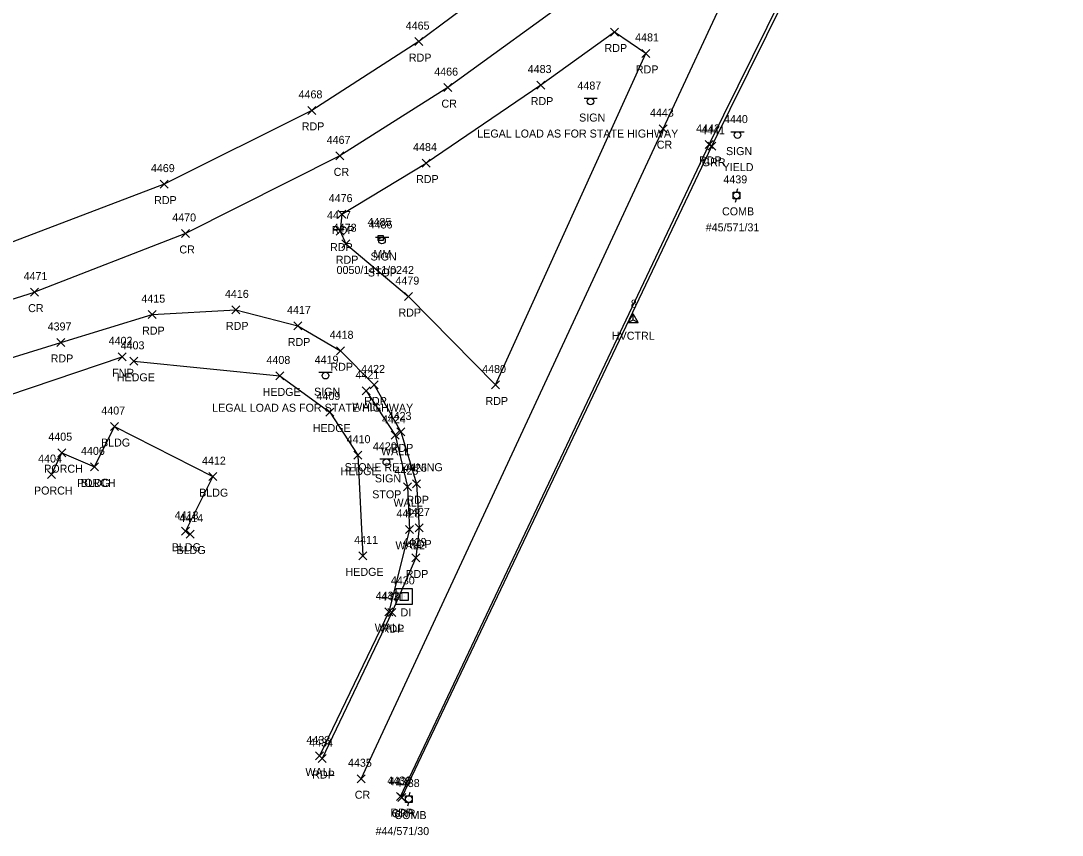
# Model space of a CAD drawing. Extents: x 1690689 to 1696275, y 438760 to 444007.
# Drawn here: x 1696011 to 1696271.3, y 443474.4 to 443678 of the extents above; entities that cross this region are included whole.
import ezdxf

# ---------------------------------------------------------------- set-up
doc = ezdxf.new("R2010")
doc.units = 0
for name, color, linetype in [('C_A', 7, 'Continuous'), ('C_I', 7, 'Continuous'), ('CPSM', 7, 'Continuous'), ('D_A', 7, 'Continuous'), ('D_I', 7, 'Continuous'), ('DS', 7, 'Continuous'), ('L_A', 7, 'Continuous'), ('L_C', 7, 'Continuous'), ('L_I', 7, 'Continuous'), ('L_TIC', 7, 'Continuous'), ('LAHR', 7, 'Continuous'), ('LBC', 7, 'Continuous'), ('LBF', 7, 'Continuous'), ('LFNC', 7, 'Continuous'), ('LW', 7, 'Continuous'), ('P_A', 7, 'Continuous'), ('P_I', 7, 'Continuous'), ('P_TIC', 7, 'Continuous'), ('PET', 7, 'Continuous'), ('PRC', 7, 'Continuous'), ('R_A', 7, 'Continuous'), ('R_I', 7, 'Continuous'), ('R_TIC', 7, 'Continuous'), ('RGR', 7, 'Continuous'), ('S_A', 7, 'Continuous'), ('S_C', 7, 'Continuous'), ('S_I', 7, 'Continuous'), ('SRM', 7, 'Continuous'), ('SSGN', 7, 'Continuous'), ('U_A', 7, 'Continuous'), ('U_C', 7, 'Continuous'), ('U_I', 7, 'Continuous'), ('UP', 7, 'Continuous')]:
    doc.layers.add(name, color=color, linetype=linetype)

msp = doc.modelspace()

# ---------------------------------------------------------------- linework, layer by layer
at = {"layer": 'CPSM'}
for p, q in [((1696162.82, 443602.55), (1696164.07, 443604.72)), ((1696165.32, 443602.55), (1696164.07, 443604.72)), ((1696164.07, 443603.27), (1696164.07, 443604.72)), ((1696162.82, 443602.55), (1696164.07, 443603.27)), ((1696162.82, 443602.55), (1696165.32, 443602.55)), ((1696164.07, 443603.27), (1696164.07, 443603.27)), ((1696164.07, 443603.27), (1696165.32, 443602.55))]:
    msp.add_line(p, q, dxfattribs=at)
at = {"layer": 'DS'}
for p, q in [((1696104.89, 443536.11), (1696108.89, 443536.11)), ((1696104.89, 443532.11), (1696104.89, 443536.11)), ((1696108.89, 443536.11), (1696108.89, 443532.11)), ((1696105.89, 443533.11), (1696105.89, 443535.11)), ((1696105.89, 443535.11), (1696107.89, 443535.11)), ((1696107.89, 443533.11), (1696105.89, 443533.11)), ((1696106.89, 443534.11), (1696106.89, 443534.11)), ((1696106.89, 443534.11), (1696106.89, 443534.11)), ((1696107.89, 443535.11), (1696107.89, 443533.11)), ((1696108.89, 443532.11), (1696104.89, 443532.11))]:
    msp.add_line(p, q, dxfattribs=at)
at = {"layer": 'L_TIC'}
for points in [[(1696035.34, 443593), (1696037.34, 443595)], [(1696037.34, 443593), (1696035.34, 443595)], [(1696038.33, 443591.87), (1696040.33, 443593.87)], [(1696040.33, 443591.87), (1696038.33, 443593.87)], [(1696074.78, 443588.22), (1696076.78, 443590.22)], [(1696076.78, 443588.22), (1696074.78, 443590.22)], [(1696096.39, 443584.51), (1696098.39, 443586.51)], [(1696098.39, 443584.51), (1696096.39, 443586.51)], [(1696087.29, 443579.19), (1696089.29, 443581.19)], [(1696089.29, 443579.19), (1696087.29, 443581.19)], [(1696033.49, 443575.57), (1696035.49, 443577.57)], [(1696035.49, 443575.57), (1696033.49, 443577.57)], [(1696103.57, 443573.41), (1696105.57, 443575.41)], [(1696105.57, 443573.41), (1696103.57, 443575.41)], [(1696020.26, 443569.03), (1696022.26, 443571.03)], [(1696022.26, 443569.03), (1696020.26, 443571.03)], [(1696094.26, 443568.41), (1696096.26, 443570.41)], [(1696096.26, 443568.41), (1696094.26, 443570.41)], [(1696028.48, 443565.48), (1696030.48, 443567.48)], [(1696030.48, 443565.48), (1696028.48, 443567.48)], [(1696028.48, 443565.48), (1696030.48, 443567.48)], [(1696030.48, 443565.48), (1696028.48, 443567.48)], [(1696017.71, 443563.57), (1696019.71, 443565.57)], [(1696019.71, 443563.57), (1696017.71, 443565.57)], [(1696058.02, 443563.04), (1696060.02, 443565.04)], [(1696060.02, 443563.04), (1696058.02, 443565.04)], [(1696106.71, 443560.53), (1696108.71, 443562.53)], [(1696108.71, 443560.53), (1696106.71, 443562.53)], [(1696051.18, 443549.4), (1696053.18, 443551.4)], [(1696053.18, 443549.4), (1696051.18, 443551.4)], [(1696107.19, 443549.86), (1696109.19, 443551.86)], [(1696109.19, 443549.86), (1696107.19, 443551.86)], [(1696052.36, 443548.69), (1696054.36, 443550.69)], [(1696054.36, 443548.69), (1696052.36, 443550.69)], [(1696095.5, 443543.24), (1696097.5, 443545.24)], [(1696097.5, 443543.24), (1696095.5, 443545.24)], [(1696102.01, 443529.28), (1696104.01, 443531.28)], [(1696104.01, 443529.28), (1696102.01, 443531.28)], [(1696084.68, 443493.22), (1696086.68, 443495.22)], [(1696086.68, 443493.22), (1696084.68, 443495.22)]]:
    msp.add_lwpolyline(points, dxfattribs=at)
at = {"layer": 'LAHR'}
msp.add_lwpolyline([(1696039.33, 443592.87), (1696075.78, 443589.22), (1696088.29, 443580.19), (1696095.26, 443569.41), (1696096.5, 443544.24)], dxfattribs=at)
at = {"layer": 'LBC'}
msp.add_lwpolyline([(1696029.48, 443566.48), (1696034.49, 443576.57), (1696059.02, 443564.04), (1696052.18, 443550.4), (1696053.36, 443549.69)], dxfattribs=at)
at = {"layer": 'LBF'}
msp.add_lwpolyline([(1696018.71, 443564.57), (1696021.26, 443570.03), (1696029.48, 443566.48)], dxfattribs=at)
at = {"layer": 'LFNC'}
msp.add_lwpolyline([(1695959.01, 443561.01), (1695960.28, 443568.97), (1695966.01, 443573.58), (1695990.72, 443578.55), (1696036.34, 443594)], dxfattribs=at)
at = {"layer": 'LW'}
msp.add_lwpolyline([(1696097.39, 443585.51), (1696104.57, 443574.41), (1696107.71, 443561.53), (1696108.19, 443550.86), (1696103.01, 443530.28), (1696085.68, 443494.22)], dxfattribs=at)
at = {"layer": 'P_TIC'}
for points in [[(1696109.55, 443671.79), (1696111.55, 443673.79)], [(1696111.55, 443671.79), (1696109.55, 443673.79)], [(1696158.44, 443674.19), (1696160.44, 443676.19)], [(1696160.44, 443674.19), (1696158.44, 443676.19)], [(1696166.28, 443668.85), (1696168.28, 443670.85)], [(1696168.28, 443668.85), (1696166.28, 443670.85)], [(1696116.73, 443660.29), (1696118.73, 443662.29)], [(1696118.73, 443660.29), (1696116.73, 443662.29)], [(1696139.99, 443660.93), (1696141.99, 443662.93)], [(1696141.99, 443660.93), (1696139.99, 443662.93)], [(1696082.77, 443654.61), (1696084.77, 443656.61)], [(1696084.77, 443654.61), (1696082.77, 443656.61)], [(1696170.55, 443650.03), (1696172.55, 443652.03)], [(1696172.55, 443650.03), (1696170.55, 443652.03)], [(1696182.09, 443646.09), (1696184.09, 443648.09)], [(1696184.09, 443646.09), (1696182.09, 443648.09)], [(1696089.79, 443643.23), (1696091.79, 443645.23)], [(1696091.79, 443643.23), (1696089.79, 443645.23)], [(1696111.34, 443641.44), (1696113.34, 443643.44)], [(1696113.34, 443641.44), (1696111.34, 443643.44)], [(1696111.34, 443641.44), (1696113.34, 443643.44)], [(1696113.34, 443641.44), (1696111.34, 443643.44)], [(1696045.88, 443636.17), (1696047.88, 443638.17)], [(1696047.88, 443636.17), (1696045.88, 443638.17)], [(1696090.31, 443628.67), (1696092.31, 443630.67)], [(1696092.31, 443628.67), (1696090.31, 443630.67)], [(1696090.31, 443628.67), (1696092.31, 443630.67)], [(1696092.31, 443628.67), (1696090.31, 443630.67)], [(1696051.24, 443623.84), (1696053.24, 443625.84)], [(1696053.24, 443623.84), (1696051.24, 443625.84)], [(1696089.83, 443624.42), (1696091.83, 443626.42)], [(1696091.83, 443624.42), (1696089.83, 443626.42)], [(1696091.28, 443621.27), (1696093.28, 443623.27)], [(1696093.28, 443621.27), (1696091.28, 443623.27)], [(1696013.43, 443609.17), (1696015.43, 443611.17)], [(1696015.43, 443609.17), (1696013.43, 443611.17)], [(1696013.43, 443609.17), (1696015.43, 443611.17)], [(1696015.43, 443609.17), (1696013.43, 443611.17)], [(1696106.95, 443608.05), (1696108.95, 443610.05)], [(1696108.95, 443608.05), (1696106.95, 443610.05)], [(1696063.81, 443604.73), (1696065.81, 443606.73)], [(1696065.81, 443604.73), (1696063.81, 443606.73)], [(1696042.87, 443603.54), (1696044.87, 443605.54)], [(1696044.87, 443603.54), (1696042.87, 443605.54)], [(1696079.27, 443600.71), (1696081.27, 443602.71)], [(1696081.27, 443600.71), (1696079.27, 443602.71)], [(1696020.01, 443596.59), (1696022.01, 443598.59)], [(1696022.01, 443596.59), (1696020.01, 443598.59)], [(1696089.93, 443594.5), (1696091.93, 443596.5)], [(1696091.93, 443594.5), (1696089.93, 443596.5)], [(1696098.38, 443585.97), (1696100.38, 443587.97)], [(1696100.38, 443585.97), (1696098.38, 443587.97)], [(1696128.69, 443585.96), (1696130.69, 443587.96)], [(1696130.69, 443585.96), (1696128.69, 443587.96)], [(1696104.99, 443574.22), (1696106.99, 443576.22)], [(1696106.99, 443574.22), (1696104.99, 443576.22)], [(1696108.92, 443561.26), (1696110.92, 443563.26)], [(1696110.92, 443561.26), (1696108.92, 443563.26)], [(1696109.58, 443550.23), (1696111.58, 443552.23)], [(1696111.58, 443550.23), (1696109.58, 443552.23)], [(1696108.75, 443542.71), (1696110.75, 443544.71)], [(1696110.75, 443542.71), (1696108.75, 443544.71)], [(1696102.75, 443529.05), (1696104.75, 443531.05)], [(1696104.75, 443529.05), (1696102.75, 443531.05)], [(1696085.38, 443492.57), (1696087.38, 443494.57)], [(1696087.38, 443492.57), (1696085.38, 443494.57)], [(1696095.07, 443487.52), (1696097.07, 443489.52)], [(1696097.07, 443487.52), (1696095.07, 443489.52)], [(1696104.95, 443483.07), (1696106.95, 443485.07)], [(1696106.95, 443483.07), (1696104.95, 443485.07)]]:
    msp.add_lwpolyline(points, dxfattribs=at)
at = {"layer": 'PET'}
for points in [[(1696250.19, 443791.3), (1696210.71, 443754.93), (1696170.77, 443719.49), (1696142.82, 443696.93), (1696110.55, 443672.79), (1696083.77, 443655.61), (1696046.88, 443637.17), (1696007.3, 443622.08), (1695975.79, 443612.67), (1695948.64, 443606.07)], [(1696105.95, 443484.07), (1696183.09, 443647.09), (1696201.23, 443683.9), (1696215.73, 443708.5), (1696230.46, 443732.21), (1696245.32, 443748.71), (1696270.65, 443772.67)], [(1696091.31, 443629.67), (1696090.83, 443625.42), (1696092.28, 443622.27), (1696107.95, 443609.05), (1696129.69, 443586.96), (1696167.28, 443669.85), (1696159.44, 443675.19), (1696140.99, 443661.93), (1696112.34, 443642.44)], [(1696091.31, 443629.67), (1696112.34, 443642.44)], [(1695434.73, 443581.93), (1695585.07, 443568.57), (1695628.56, 443565.03), (1695681.69, 443563.93), (1695757.52, 443561.13), (1695790.37, 443560.66), (1695853.12, 443561.12), (1695890.45, 443563.92), (1695919.82, 443567.87), (1695957.52, 443577.66), (1695993.2, 443588.96), (1696021.01, 443597.59), (1696043.87, 443604.54), (1696064.81, 443605.73), (1696080.27, 443601.71), (1696090.93, 443595.5), (1696099.38, 443586.97), (1696105.99, 443575.22), (1696109.92, 443562.26), (1696110.58, 443551.23), (1696109.75, 443543.71), (1696103.75, 443530.05), (1696086.38, 443493.57)]]:
    msp.add_lwpolyline(points, dxfattribs=at)
at = {"layer": 'PRC'}
for points in [[(1696260.51, 443781.47), (1696219.19, 443743.86), (1696178.48, 443707.8), (1696151.38, 443685.72), (1696117.73, 443661.29), (1696090.79, 443644.23), (1696052.24, 443624.84), (1696014.43, 443610.17)], [(1696096.07, 443488.52), (1696171.55, 443651.03), (1696188.46, 443687.38), (1696195.87, 443702.85)], [(1694248.41, 443577.88), (1694744.61, 443600.37), (1695048.23, 443613.58), (1695105.82, 443614.96), (1695173.44, 443615.81), (1695246.74, 443615.27), (1695303.17, 443612.95), (1695350.61, 443610.59), (1695437.58, 443604.58), (1695599.23, 443591.28), (1695682.53, 443585.47), (1695756.48, 443581.73), (1695791.02, 443580.47), (1695851.39, 443580.96), (1695889.48, 443583.34), (1695926.07, 443588.21), (1695955.33, 443593.52), (1695988.94, 443602.15), (1696014.43, 443610.17)]]:
    msp.add_lwpolyline(points, dxfattribs=at)
at = {"layer": 'R_TIC'}
for points in [[(1696182.75, 443645.63), (1696184.75, 443647.63)], [(1696184.75, 443645.63), (1696182.75, 443647.63)], [(1696105.25, 443482.86), (1696107.25, 443484.86)], [(1696107.25, 443482.86), (1696105.25, 443484.86)]]:
    msp.add_lwpolyline(points, dxfattribs=at)
at = {"layer": 'RGR'}
msp.add_lwpolyline([(1696106.25, 443483.86), (1696183.75, 443646.63), (1696202.1, 443683.72), (1696216.25, 443708.09), (1696231.62, 443731.39), (1696245.68, 443748.04), (1696271.31, 443772.35)], dxfattribs=at)
at = {"layer": 'SRM'}
msp.add_lwpolyline([(1696100.34, 443624.33), (1696101.59, 443624.33), (1696101.59, 443623.08), (1696100.34, 443623.08)], close=True, dxfattribs=at)
msp.add_circle((1696100.97, 443623.71), 0.0833, dxfattribs=at)
at = {"layer": 'SSGN'}
for p, q in [((1696151.8, 443658.67), (1696155.13, 443658.67)), ((1696153.44, 443657.84), (1696153.44, 443657.84)), ((1696188.51, 443650.27), (1696191.84, 443650.27)), ((1696190.15, 443649.44), (1696190.15, 443649.44)), ((1696099.66, 443623.93), (1696103, 443623.93)), ((1696101.31, 443623.1), (1696101.31, 443623.1)), ((1696085.55, 443590.12), (1696088.88, 443590.12)), ((1696087.2, 443589.29), (1696087.2, 443589.29)), ((1696100.76, 443568.47), (1696104.09, 443568.47)), ((1696102.41, 443567.64), (1696102.41, 443567.64))]:
    msp.add_line(p, q, dxfattribs=at)
for centre in [(1696153.44, 443657.84), (1696190.15, 443649.44), (1696101.31, 443623.1), (1696087.2, 443589.29), (1696102.41, 443567.64)]:
    msp.add_circle(centre, 0.833, dxfattribs=at)
at = {"layer": 'UP'}
for p, q in [((1696189.07, 443633.53), (1696189.07, 443635.19)), ((1696189.07, 443635.19), (1696190.74, 443635.19)), ((1696190.15, 443636.03), (1696189.9, 443635.19)), ((1696190.74, 443635.19), (1696190.74, 443633.53)), ((1696190.74, 443633.53), (1696189.07, 443633.53)), ((1696189.65, 443632.69), (1696189.9, 443633.53)), ((1696189.9, 443634.36), (1696189.9, 443634.36)), ((1696107.2, 443482.61), (1696107.2, 443484.28)), ((1696107.2, 443484.28), (1696108.87, 443484.28)), ((1696108.28, 443485.11), (1696108.03, 443484.28)), ((1696108.87, 443484.28), (1696108.87, 443482.61)), ((1696108.87, 443482.61), (1696107.2, 443482.61)), ((1696107.78, 443481.78), (1696108.03, 443482.61)), ((1696108.03, 443483.44), (1696108.03, 443483.44))]:
    msp.add_line(p, q, dxfattribs=at)
for centre in [(1696189.9, 443634.36), (1696108.03, 443483.44)]:
    msp.add_circle(centre, 0.833, dxfattribs=at)

# ---------------------------------------------------------------- texts
at = {"layer": 'C_A'}
msp.add_text('HVCTRL', height=2, dxfattribs=at).set_placement((1696158.76, 443598.27))
at = {"layer": 'C_I'}
msp.add_text('8', height=2, dxfattribs=at).set_placement((1696163.5, 443606.27))
at = {"layer": 'D_A'}
msp.add_text('DI', height=2, dxfattribs=at).set_placement((1696105.95, 443529.11))
at = {"layer": 'D_I'}
msp.add_text('4430', height=2, dxfattribs=at).set_placement((1696103.54, 443537.11))
at = {"layer": 'L_A'}
for s, p in [('FNR', (1696033.87, 443589)), ('HEDGE', (1696035.03, 443587.87)), ('HEDGE', (1696071.48, 443584.22)), ('WALL', (1696093.88, 443580.51)), ('HEDGE', (1696083.99, 443575.19)), ('BLDG', (1696031.08, 443571.57)), ('WALL', (1696101.06, 443569.41)), ('PORCH', (1696016.88, 443565.03)), ('HEDGE', (1696090.96, 443564.41)), ('PORCH', (1696025.1, 443561.48)), ('BLDG', (1696026.07, 443561.48)), ('PORCH', (1696014.33, 443559.57)), ('BLDG', (1696055.61, 443559.04)), ('WALL', (1696104.19, 443556.53)), ('BLDG', (1696048.77, 443545.4)), ('BLDG', (1696049.96, 443544.69)), ('WALL', (1696104.68, 443545.86)), ('HEDGE', (1696092.2, 443539.24)), ('WALL', (1696099.5, 443525.28)), ('WALL', (1696082.17, 443489.22))]:
    msp.add_text(s, height=2, dxfattribs=at).set_placement(p)
at = {"layer": 'L_C'}
msp.add_text('STONE RETAINING', height=2, dxfattribs=at).set_placement((1696091.97, 443565.41))
at = {"layer": 'L_I'}
for s, p in [('4402', (1696033, 443597)), ('4403', (1696035.99, 443595.87)), ('4408', (1696072.44, 443592.22)), ('4421', (1696094.7, 443588.51)), ('4409', (1696084.94, 443583.19)), ('4407', (1696031.16, 443579.57)), ('4424', (1696101.31, 443577.41)), ('4405', (1696017.92, 443573.03)), ('4410', (1696092.48, 443572.41)), ('4404', (1696015.37, 443567.57)), ('4406', (1696026.09, 443569.48)), ('4406', (1696026.09, 443569.48)), ('4412', (1696056.33, 443567.04)), ('4425', (1696104.45, 443564.53)), ('4413', (1696049.49, 443553.4)), ('4414', (1696050.67, 443552.69)), ('4428', (1696104.93, 443553.86)), ('4411', (1696094.37, 443547.24)), ('4432', (1696099.75, 443533.28)), ('4433', (1696082.42, 443497.22))]:
    msp.add_text(s, height=2, dxfattribs=at).set_placement(p)
at = {"layer": 'P_A'}
for s, p in [('RDP', (1696156.93, 443670.19)), ('RDP', (1696108.03, 443667.79)), ('RDP', (1696164.76, 443664.85)), ('CR', (1696116.17, 443656.29)), ('RDP', (1696138.48, 443656.93)), ('RDP', (1696081.26, 443650.61)), ('CR', (1696169.98, 443646.03)), ('RDP', (1696180.57, 443642.09)), ('CR', (1696089.23, 443639.23)), ('RDP', (1696109.83, 443637.44)), ('RDP', (1696109.83, 443637.44)), ('RDP', (1696044.37, 443632.17)), ('RDP', (1696088.8, 443624.67)), ('RDP', (1696088.8, 443624.67)), ('CR', (1696050.67, 443619.84)), ('RDP', (1696088.32, 443620.42)), ('RDP', (1696089.77, 443617.27)), ('CR', (1696012.87, 443605.17)), ('CR', (1696012.87, 443605.17)), ('RDP', (1696105.43, 443604.05)), ('RDP', (1696041.36, 443599.54)), ('RDP', (1696062.3, 443600.73)), ('RDP', (1696077.76, 443596.71)), ('RDP', (1696018.5, 443592.59)), ('RDP', (1696088.42, 443590.5)), ('RDP', (1696096.87, 443581.97)), ('RDP', (1696127.18, 443581.96)), ('RDP', (1696103.48, 443570.22)), ('RDP', (1696107.4, 443557.26)), ('RDP', (1696108.07, 443546.23)), ('RDP', (1696107.24, 443538.71)), ('RDP', (1696101.24, 443525.05)), ('RDP', (1696083.87, 443488.57)), ('CR', (1696094.51, 443483.52)), ('RDP', (1696103.43, 443479.07))]:
    msp.add_text(s, height=2, dxfattribs=at).set_placement(p)
at = {"layer": 'P_I'}
for s, p in [('4465', (1696107.24, 443675.79)), ('4481', (1696164.58, 443672.85)), ('4466', (1696114.37, 443664.29)), ('4483', (1696137.73, 443664.93)), ('4468', (1696080.46, 443658.61)), ('4443', (1696168.29, 443654.03)), ('4442', (1696179.83, 443650.09)), ('4467', (1696087.49, 443647.23)), ('4484', (1696109.08, 443645.44)), ('4484', (1696109.08, 443645.44)), ('4469', (1696043.56, 443640.17)), ('4476', (1696088, 443632.67)), ('4476', (1696088, 443632.67)), ('4470', (1696048.89, 443627.84)), ('4477', (1696087.57, 443628.42)), ('4478', (1696089.02, 443625.27)), ('4471', (1696011.74, 443613.17)), ('4471', (1696011.74, 443613.17)), ('4479', (1696104.68, 443612.05)), ('4415', (1696041.18, 443607.54)), ('4416', (1696062.06, 443608.73)), ('4417', (1696077.58, 443604.71)), ('4397', (1696017.75, 443600.59)), ('4418', (1696088.24, 443598.5)), ('4422', (1696096.12, 443589.97)), ('4480', (1696126.35, 443589.96)), ('4423', (1696102.73, 443578.22)), ('4426', (1696106.6, 443565.26)), ('4427', (1696107.32, 443554.23)), ('4429', (1696106.49, 443546.71)), ('4431', (1696101.06, 443533.05)), ('4434', (1696083.12, 443496.57)), ('4435', (1696092.81, 443491.52)), ('4436', (1696102.63, 443487.07))]:
    msp.add_text(s, height=2, dxfattribs=at).set_placement(p)
at = {"layer": 'R_A'}
for p in [(1696181.24, 443641.63), (1696103.74, 443478.86)]:
    msp.add_text('GRR', height=2, dxfattribs=at).set_placement(p)
at = {"layer": 'R_I'}
for s, p in [('4441', (1696181.05, 443649.63)), ('4437', (1696102.99, 443486.86))]:
    msp.add_text(s, height=2, dxfattribs=at).set_placement(p)
at = {"layer": 'S_A'}
for s, p in [('SIGN', (1696150.58, 443652.81)), ('SIGN', (1696187.29, 443644.42)), ('SIGN', (1696098.45, 443618.08)), ('MM', (1696099.16, 443618.71)), ('SIGN', (1696084.33, 443584.27)), ('SIGN', (1696099.54, 443562.62))]:
    msp.add_text(s, height=2, dxfattribs=at).set_placement(p)
at = {"layer": 'S_C'}
for s, p in [('LEGAL LOAD AS FOR STATE HIGHWAY', (1696125.12, 443648.81)), ('YIELD', (1696186.42, 443640.42)), ('0050/1411/0242', (1696089.96, 443614.71)), ('STOP', (1696097.77, 443614.08)), ('LEGAL LOAD AS FOR STATE HIGHWAY', (1696058.88, 443580.27)), ('STOP', (1696098.87, 443558.62))]:
    msp.add_text(s, height=2, dxfattribs=at).set_placement(p)
at = {"layer": 'S_I'}
for s, p in [('4487', (1696150.16, 443660.81)), ('4440', (1696186.79, 443652.42)), ('4485', (1696097.71, 443626.71)), ('4486', (1696097.97, 443626.08)), ('4419', (1696084.48, 443592.27)), ('4420', (1696099.04, 443570.62))]:
    msp.add_text(s, height=2, dxfattribs=at).set_placement(p)
at = {"layer": 'U_A'}
for p in [(1696186.29, 443629.36), (1696104.42, 443478.44)]:
    msp.add_text('COMB', height=2, dxfattribs=at).set_placement(p)
at = {"layer": 'U_C'}
for s, p in [('#45/571/31', (1696182.23, 443625.36)), ('#44/571/30', (1696099.71, 443474.44))]:
    msp.add_text(s, height=2, dxfattribs=at).set_placement(p)
at = {"layer": 'U_I'}
for s, p in [('4439', (1696186.64, 443637.36)), ('4438', (1696104.78, 443486.44))]:
    msp.add_text(s, height=2, dxfattribs=at).set_placement(p)

doc.saveas('drawing.dxf')
